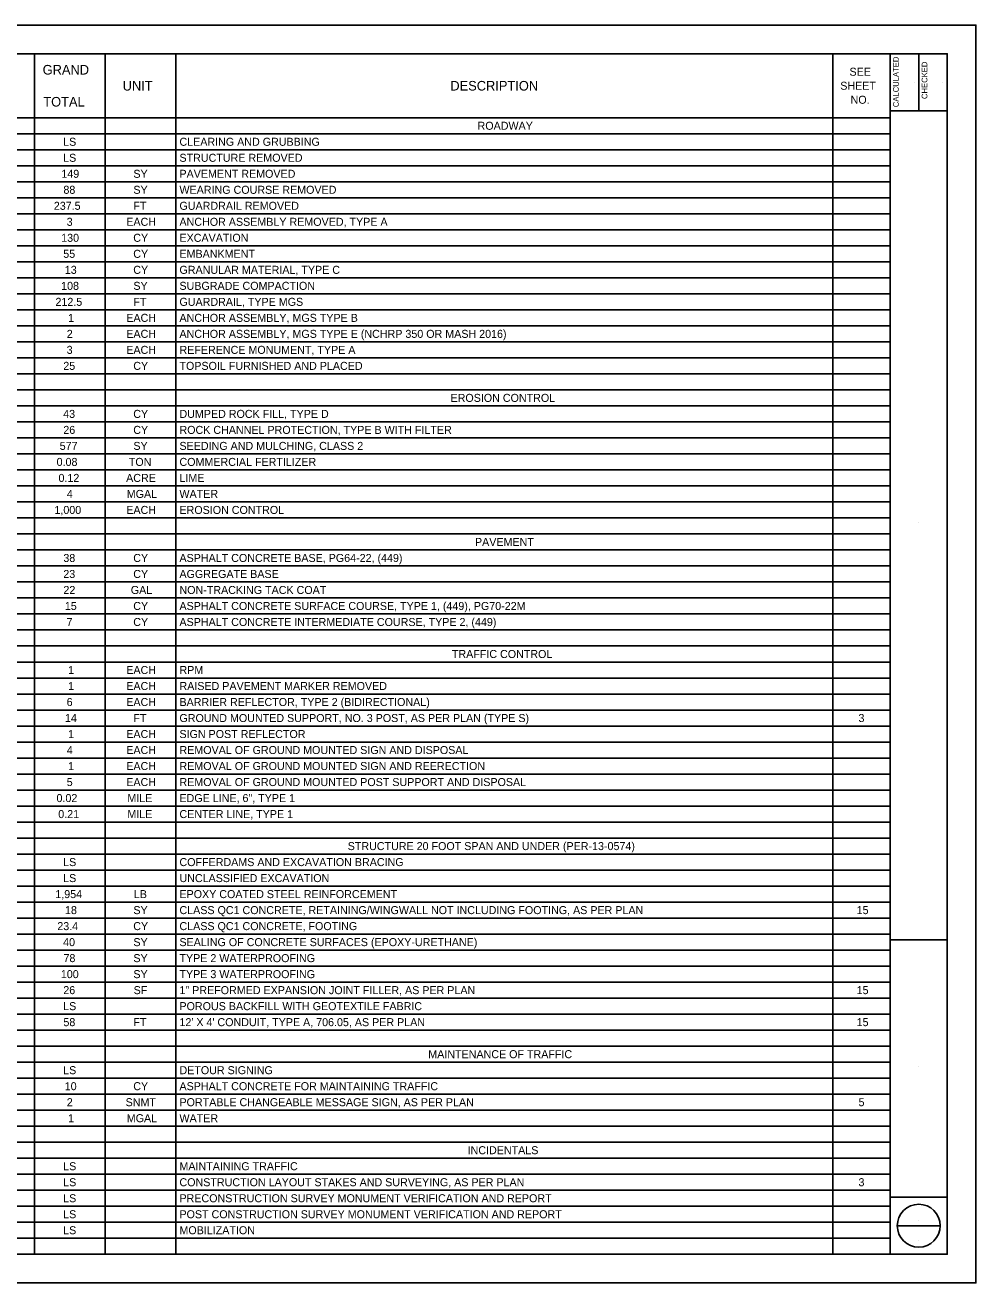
# Model space of a CAD drawing. Extents: x 0 to 34, y 0 to 22.
# Drawn here: x 17.37 to 34, y 0 to 22 of the extents above; entities that cross this region are included whole.
import ezdxf

# ---------------------------------------------------------------- set-up
doc = ezdxf.new("R2010")
doc.units = 0
for name, color, linetype in [('SH_Border', 7, 'Continuous'), ('SH_Cut_Line', 7, 'Continuous'), ('SH_Data', 7, 'Continuous'), ('SH_Text', 7, 'Continuous')]:
    doc.layers.add(name, color=color, linetype=linetype)

msp = doc.modelspace()

# ---------------------------------------------------------------- linework, layer by layer
at = {"layer": 'SH_Border'}
for p, q in [((32.5, 0.5), (32.5, 21.5)), ((33, 21.5), (33, 20.5)), ((32.5, 20.5), (33.5, 20.5)), ((32.5, 6), (33.5, 6)), ((32.5, 1.5), (33.5, 1.5))]:
    msp.add_line(p, q, dxfattribs=at)
msp.add_lwpolyline([(2, 21.5), (33.5, 21.5), (33.5, 0.5), (2, 0.5)], close=True, dxfattribs=at)
at = {"layer": 'SH_Cut_Line'}
msp.add_lwpolyline([(0, 0), (34, 0), (34, 22), (0, 22)], close=True, dxfattribs=at)
at = {"layer": 'SH_Data'}
for p, q in [((2, 21.5), (32.504, 21.5)), ((17.532, 21.5), (17.532, 0.5)), ((18.767, 21.5), (18.767, 0.5)), ((20.002, 21.5), (20.002, 0.5)), ((31.499, 21.5), (31.499, 0.5)), ((32.504, 21.5), (32.504, 0.5)), ((32.92, 21.004), (32.92, 21.004)), ((33.42, 21.004), (33.42, 21.004)), ((2, 20.38), (32.504, 20.38)), ((2, 20.1), (32.504, 20.1)), ((2, 19.82), (32.504, 19.82)), ((2, 19.54), (32.504, 19.54)), ((2, 19.26), (32.504, 19.26)), ((2, 18.98), (32.504, 18.98)), ((2, 18.7), (32.504, 18.7)), ((2, 18.42), (32.504, 18.42)), ((2, 18.14), (32.504, 18.14)), ((2, 17.86), (32.504, 17.86)), ((2, 17.58), (32.504, 17.58)), ((2, 17.3), (32.504, 17.3)), ((2, 17.02), (32.504, 17.02)), ((2, 16.74), (32.504, 16.74)), ((2, 16.46), (32.504, 16.46)), ((2, 16.18), (32.504, 16.18)), ((2, 15.9), (32.504, 15.9)), ((2, 15.62), (32.504, 15.62)), ((2, 15.34), (32.504, 15.34)), ((2, 15.06), (32.504, 15.06)), ((2, 14.78), (32.504, 14.78)), ((2, 14.5), (32.504, 14.5)), ((2, 14.22), (32.504, 14.22)), ((2, 13.94), (32.504, 13.94)), ((2, 13.66), (32.504, 13.66)), ((2, 13.38), (32.504, 13.38)), ((33, 13.292), (33, 13.292)), ((2, 13.1), (32.504, 13.1)), ((2, 12.82), (32.504, 12.82)), ((2, 12.54), (32.504, 12.54)), ((2, 12.26), (32.504, 12.26)), ((2, 11.98), (32.504, 11.98)), ((2, 11.7), (32.504, 11.7)), ((2, 11.42), (32.504, 11.42)), ((2, 11.14), (32.504, 11.14)), ((2, 10.86), (32.504, 10.86)), ((2, 10.58), (32.504, 10.58)), ((2, 10.3), (32.504, 10.3)), ((2, 10.02), (32.504, 10.02)), ((2, 9.74), (32.504, 9.74)), ((2, 9.46), (32.504, 9.46)), ((2, 9.18), (32.504, 9.18)), ((2, 8.9), (32.504, 8.9)), ((2, 8.62), (32.504, 8.62)), ((2, 8.34), (32.504, 8.34)), ((2, 8.06), (32.504, 8.06)), ((2, 7.78), (32.504, 7.78)), ((2, 7.5), (32.504, 7.5)), ((2, 7.22), (32.504, 7.22)), ((2, 6.94), (32.504, 6.94)), ((2, 6.66), (32.504, 6.66)), ((2, 6.38), (32.504, 6.38)), ((2, 6.1), (32.504, 6.1)), ((2, 5.82), (32.504, 5.82)), ((2, 5.54), (32.504, 5.54)), ((2, 5.26), (32.504, 5.26)), ((2, 4.98), (32.504, 4.98)), ((2, 4.7), (32.504, 4.7)), ((2, 4.42), (32.504, 4.42)), ((2, 4.14), (32.504, 4.14)), ((2, 3.86), (32.504, 3.86)), ((33, 3.792), (33, 3.792)), ((2, 3.58), (32.504, 3.58)), ((2, 3.3), (32.504, 3.3)), ((2, 3.02), (32.504, 3.02)), ((2, 2.74), (32.504, 2.74)), ((2, 2.46), (32.504, 2.46)), ((2, 2.18), (32.504, 2.18)), ((2, 1.9), (32.504, 1.9)), ((2, 1.62), (32.504, 1.62)), ((2, 1.34), (32.504, 1.34)), ((2, 1.06), (32.504, 1.06)), ((32.625, 1), (33.375, 1)), ((33, 1.085), (33, 1.085)), ((2, 0.78), (32.504, 0.78)), ((33, 0.745), (33, 0.745)), ((2, 0.5), (32.504, 0.5))]:
    msp.add_line(p, q, dxfattribs=at)
msp.add_circle((33, 1), 0.375, dxfattribs=at)

# ---------------------------------------------------------------- texts
for s, p in [('CALCULATED', (32.652, 20.565)), ('CHECKED', (33.152, 20.708))]:
    msp.add_text(s, height=0.1, rotation=90, dxfattribs=at).set_placement(p)
at = {"layer": 'SH_Text'}
for s, height, p in [('GRAND', 0.168, (17.675, 21.136)), ('SEE', 0.14, (31.79, 21.115)), ('UNIT', 0.168, (19.075, 20.856)), ('DESCRIPTION', 0.168, (24.807, 20.856)), ('SHEET', 0.14, (31.628, 20.87)), ('TOTAL', 0.168, (17.686, 20.576)), ('NO.', 0.14, (31.809, 20.625)), ('ROADWAY', 0.14, (25.283, 20.17)), ('LS', 0.14, (18.034, 19.89)), ('CLEARING AND GRUBBING', 0.14, (20.068, 19.89)), ('LS', 0.14, (18.034, 19.61)), ('STRUCTURE REMOVED', 0.14, (20.068, 19.61)), ('149', 0.14, (18.002, 19.33)), ('SY', 0.14, (19.262, 19.33)), ('PAVEMENT REMOVED', 0.14, (20.068, 19.33)), ('88', 0.14, (18.038, 19.05)), ('SY', 0.14, (19.262, 19.05)), ('WEARING COURSE REMOVED', 0.14, (20.068, 19.05)), ('237.5', 0.14, (17.87, 18.77)), ('FT', 0.14, (19.262, 18.77)), ('GUARDRAIL REMOVED', 0.14, (20.068, 18.77)), ('3', 0.14, (18.095, 18.49)), ('EACH', 0.14, (19.138, 18.49)), ('ANCHOR ASSEMBLY REMOVED, TYPE A', 0.14, (20.068, 18.49)), ('130', 0.14, (17.999, 18.21)), ('CY', 0.14, (19.26, 18.21)), ('EXCAVATION', 0.14, (20.068, 18.21)), ('55', 0.14, (18.035, 17.93)), ('CY', 0.14, (19.26, 17.93)), ('EMBANKMENT', 0.14, (20.068, 17.93)), ('13', 0.14, (18.062, 17.65)), ('CY', 0.14, (19.26, 17.65)), ('GRANULAR MATERIAL, TYPE C', 0.14, (20.068, 17.65)), ('108', 0.14, (17.998, 17.37)), ('SY', 0.14, (19.262, 17.37)), ('SUBGRADE COMPACTION', 0.14, (20.068, 17.37)), ('212.5', 0.14, (17.899, 17.09)), ('FT', 0.14, (19.262, 17.09)), ('GUARDRAIL, TYPE MGS', 0.14, (20.068, 17.09)), ('1', 0.14, (18.12, 16.81)), ('EACH', 0.14, (19.138, 16.81)), ('ANCHOR ASSEMBLY, MGS TYPE B', 0.14, (20.068, 16.81)), ('2', 0.14, (18.097, 16.53)), ('EACH', 0.14, (19.138, 16.53)), ('ANCHOR ASSEMBLY, MGS TYPE E (NCHRP 350 OR MASH 2016)', 0.14, (20.068, 16.53)), ('3', 0.14, (18.095, 16.25)), ('EACH', 0.14, (19.138, 16.25)), ('REFERENCE MONUMENT, TYPE A', 0.14, (20.068, 16.25)), ('25', 0.14, (18.036, 15.97)), ('CY', 0.14, (19.26, 15.97)), ('TOPSOIL FURNISHED AND PLACED', 0.14, (20.068, 15.97)), ('EROSION CONTROL', 0.14, (24.81, 15.41)), ('43', 0.14, (18.034, 15.13)), ('CY', 0.14, (19.26, 15.13)), ('DUMPED ROCK FILL, TYPE D', 0.14, (20.068, 15.13)), ('26', 0.14, (18.036, 14.85)), ('CY', 0.14, (19.26, 14.85)), ('ROCK CHANNEL PROTECTION, TYPE B WITH FILTER', 0.14, (20.068, 14.85)), ('577', 0.14, (17.973, 14.57)), ('SY', 0.14, (19.262, 14.57)), ('SEEDING AND MULCHING, CLASS 2', 0.14, (20.068, 14.57)), ('0.08', 0.14, (17.919, 14.29)), ('TON', 0.14, (19.182, 14.29)), ('COMMERCIAL FERTILIZER', 0.14, (20.068, 14.29)), ('0.12', 0.14, (17.952, 14.01)), ('ACRE', 0.14, (19.135, 14.01)), ('LIME', 0.14, (20.068, 14.01)), ('4', 0.14, (18.098, 13.73)), ('MGAL', 0.14, (19.146, 13.73)), ('WATER', 0.14, (20.068, 13.73)), ('1,000', 0.14, (17.881, 13.45)), ('EACH', 0.14, (19.138, 13.45)), ('EROSION CONTROL', 0.14, (20.068, 13.45)), ('PAVEMENT', 0.14, (25.238, 12.89)), ('38', 0.14, (18.037, 12.61)), ('CY', 0.14, (19.26, 12.61)), ('ASPHALT CONCRETE BASE, PG64-22, (449)', 0.14, (20.068, 12.61)), ('23', 0.14, (18.036, 12.33)), ('CY', 0.14, (19.26, 12.33)), ('AGGREGATE BASE', 0.14, (20.068, 12.33)), ('22', 0.14, (18.038, 12.05)), ('GAL', 0.14, (19.217, 12.05)), ('NON-TRACKING TACK COAT', 0.14, (20.068, 12.05)), ('15', 0.14, (18.063, 11.77)), ('CY', 0.14, (19.26, 11.77)), ('ASPHALT CONCRETE SURFACE COURSE, TYPE 1, (449), PG70-22M', 0.14, (20.068, 11.77)), ('7', 0.14, (18.093, 11.49)), ('CY', 0.14, (19.26, 11.49)), ('ASPHALT CONCRETE INTERMEDIATE COURSE, TYPE 2, (449)', 0.14, (20.068, 11.49)), ('TRAFFIC CONTROL', 0.14, (24.834, 10.93)), ('1', 0.14, (18.12, 10.65)), ('EACH', 0.14, (19.138, 10.65)), ('RPM', 0.14, (20.068, 10.65)), ('1', 0.14, (18.12, 10.37)), ('EACH', 0.14, (19.138, 10.37)), ('RAISED PAVEMENT MARKER REMOVED', 0.14, (20.068, 10.37)), ('6', 0.14, (18.095, 10.09)), ('EACH', 0.14, (19.138, 10.09)), ('BARRIER REFLECTOR, TYPE 2 (BIDIRECTIONAL)', 0.14, (20.068, 10.09)), ('14', 0.14, (18.065, 9.81)), ('FT', 0.14, (19.262, 9.81)), ('GROUND MOUNTED SUPPORT, NO. 3 POST, AS PER PLAN (TYPE S)', 0.14, (20.068, 9.81)), ('3', 0.14, (31.947, 9.81)), ('1', 0.14, (18.12, 9.53)), ('EACH', 0.14, (19.138, 9.53)), ('SIGN POST REFLECTOR', 0.14, (20.068, 9.53)), ('4', 0.14, (18.098, 9.25)), ('EACH', 0.14, (19.138, 9.25)), ('REMOVAL OF GROUND MOUNTED SIGN AND DISPOSAL', 0.14, (20.068, 9.25)), ('1', 0.14, (18.12, 8.97)), ('EACH', 0.14, (19.138, 8.97)), ('REMOVAL OF GROUND MOUNTED SIGN AND REERECTION', 0.14, (20.068, 8.97)), ('5', 0.14, (18.096, 8.69)), ('EACH', 0.14, (19.138, 8.69)), ('REMOVAL OF GROUND MOUNTED POST SUPPORT AND DISPOSAL', 0.14, (20.068, 8.69)), ('0.02', 0.14, (17.917, 8.41)), ('MILE', 0.14, (19.157, 8.41)), ('EDGE LINE, 6", TYPE 1', 0.14, (20.068, 8.41)), ('0.21', 0.14, (17.948, 8.13)), ('MILE', 0.14, (19.157, 8.13)), ('CENTER LINE, TYPE 1', 0.14, (20.068, 8.13)), ('STRUCTURE 20 FOOT SPAN AND UNDER (PER-13-0574)', 0.14, (23.011, 7.57)), ('LS', 0.14, (18.034, 7.29)), ('COFFERDAMS AND EXCAVATION BRACING', 0.14, (20.068, 7.29)), ('LS', 0.14, (18.034, 7.01)), ('UNCLASSIFIED EXCAVATION', 0.14, (20.068, 7.01)), ('1,954', 0.14, (17.896, 6.73)), ('LB', 0.14, (19.27, 6.73)), ('EPOXY COATED STEEL REINFORCEMENT', 0.14, (20.068, 6.73)), ('18', 0.14, (18.066, 6.45)), ('SY', 0.14, (19.262, 6.45)), ('CLASS QC1 CONCRETE, RETAINING/WINGWALL NOT INCLUDING FOOTING, AS PER PLAN', 0.14, (20.068, 6.45)), ('15', 0.14, (31.915, 6.45)), ('23.4', 0.14, (17.931, 6.17)), ('CY', 0.14, (19.26, 6.17)), ('CLASS QC1 CONCRETE, FOOTING', 0.14, (20.068, 6.17)), ('40', 0.14, (18.033, 5.89)), ('SY', 0.14, (19.262, 5.89)), ('SEALING OF CONCRETE SURFACES (EPOXY-URETHANE)', 0.14, (20.068, 5.89)), ('78', 0.14, (18.039, 5.61)), ('SY', 0.14, (19.262, 5.61)), ('TYPE 2 WATERPROOFING', 0.14, (20.068, 5.61)), ('100', 0.14, (17.993, 5.33)), ('SY', 0.14, (19.262, 5.33)), ('TYPE 3 WATERPROOFING', 0.14, (20.068, 5.33)), ('26', 0.14, (18.036, 5.05)), ('SF', 0.14, (19.266, 5.05)), ('1" PREFORMED EXPANSION JOINT FILLER, AS PER PLAN', 0.14, (20.068, 5.05)), ('15', 0.14, (31.915, 5.05)), ('LS', 0.14, (18.034, 4.77)), ('POROUS BACKFILL WITH GEOTEXTILE FABRIC', 0.14, (20.068, 4.77)), ('58', 0.14, (18.038, 4.49)), ('FT', 0.14, (19.262, 4.49)), ("12' X 4' CONDUIT, TYPE A, 706.05, AS PER PLAN", 0.14, (20.068, 4.49)), ('15', 0.14, (31.915, 4.49)), ('MAINTENANCE OF TRAFFIC', 0.14, (24.421, 3.93)), ('LS', 0.14, (18.034, 3.65)), ('DETOUR SIGNING', 0.14, (20.068, 3.65)), ('10', 0.14, (18.061, 3.37)), ('CY', 0.14, (19.26, 3.37)), ('ASPHALT CONCRETE FOR MAINTAINING TRAFFIC', 0.14, (20.068, 3.37)), ('2', 0.14, (18.097, 3.09)), ('SNMT', 0.14, (19.126, 3.09)), ('PORTABLE CHANGEABLE MESSAGE SIGN, AS PER PLAN', 0.14, (20.068, 3.09)), ('5', 0.14, (31.948, 3.09)), ('1', 0.14, (18.12, 2.81)), ('MGAL', 0.14, (19.146, 2.81)), ('WATER', 0.14, (20.068, 2.81)), ('INCIDENTALS', 0.14, (25.109, 2.25)), ('LS', 0.14, (18.034, 1.97)), ('MAINTAINING TRAFFIC', 0.14, (20.068, 1.97)), ('LS', 0.14, (18.034, 1.69)), ('CONSTRUCTION LAYOUT STAKES AND SURVEYING, AS PER PLAN', 0.14, (20.068, 1.69)), ('3', 0.14, (31.947, 1.69)), ('LS', 0.14, (18.034, 1.41)), ('PRECONSTRUCTION SURVEY MONUMENT VERIFICATION AND REPORT', 0.14, (20.068, 1.41)), ('LS', 0.14, (18.034, 1.13)), ('POST CONSTRUCTION SURVEY MONUMENT VERIFICATION AND REPORT', 0.14, (20.068, 1.13)), ('LS', 0.14, (18.034, 0.85)), ('MOBILIZATION', 0.14, (20.068, 0.85))]:
    msp.add_text(s, height=height, dxfattribs=at).set_placement(p)

doc.saveas('drawing.dxf')
